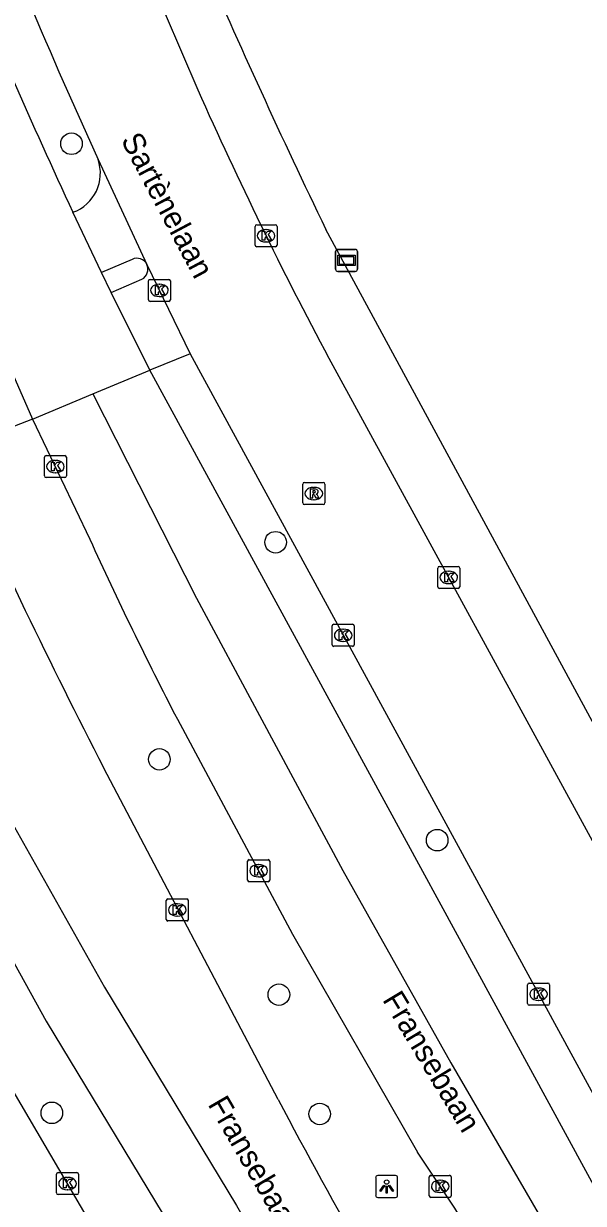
# Model space of a CAD drawing. Extents: x 157767 to 159171, y 387842 to 389425.
# Drawn here: x 158517.1 to 158542.4, y 388319.1 to 388372.6 of the extents above; entities that cross this region are included whole.
import ezdxf

# ---------------------------------------------------------------- set-up
doc = ezdxf.new("R2010")
doc.units = 0
for name, color, linetype in [('IMGEO_Boom', 7, 'Continuous'), ('IMGEO_Fietspad_open', 7, 'Continuous'), ('IMGEO_Kolk', 7, 'Continuous'), ('IMGEO_Lichtpunt', 7, 'Continuous'), ('IMGEO_Openbare_ruimte_label', 7, 'Continuous'), ('IMGEO_Rijbaan_lokaal_gesloten', 7, 'Continuous'), ('IMGEO_Rijbaan_lokaal_open', 7, 'Continuous'), ('IMGEO_Rioolput', 7, 'Continuous'), ('IMGEO_Verklikker', 7, 'Continuous'), ('IMGEO_Voetpad_open', 7, 'Continuous')]:
    doc.layers.add(name, color=color, linetype=linetype)

msp = doc.modelspace()

# ---------------------------------------------------------------- linework, layer by layer
at = {"layer": 'IMGEO_Boom'}
for centre in [(158519.228, 388367.129), (158528.486, 388349.061), (158523.215, 388339.218), (158535.816, 388335.554), (158528.635, 388328.551), (158518.336, 388323.19), (158530.487, 388323.141)]:
    msp.add_circle(centre, 0.489, dxfattribs=at)
at = {"layer": 'IMGEO_Fietspad_open'}
msp.add_lwpolyline([(158521.98, 388361.889), (158520.591, 388361.285)], dxfattribs=at)
for centre, radius, start, end in [((158518.657, 388365.792), 1.881, 289.7367, 19.4703), ((158522.198, 388361.433), 0.505, 26.5715, 115.5355)]:
    msp.add_arc(centre, radius, start, end, dxfattribs=at)
at = {"layer": 'IMGEO_Kolk'}
for p, q in [((158527.554, 388362.533), (158527.554, 388363.385)), ((158527.629, 388363.459), (158528.481, 388363.459)), ((158528.042, 388363.239), (158528.067, 388363.239)), ((158528.555, 388363.385), (158528.555, 388362.533)), ((158528.065, 388362.679), (158528.04, 388362.679)), ((158528.481, 388362.459), (158527.629, 388362.459)), ((158522.716, 388360.056), (158522.716, 388360.908)), ((158522.791, 388360.982), (158523.643, 388360.982)), ((158523.204, 388360.762), (158523.229, 388360.762)), ((158523.717, 388360.908), (158523.717, 388360.056)), ((158523.643, 388359.982), (158522.791, 388359.982)), ((158523.227, 388360.202), (158523.202, 388360.202)), ((158518.073, 388352.993), (158518.925, 388352.993)), ((158517.998, 388352.067), (158517.998, 388352.919)), ((158518.486, 388352.773), (158518.511, 388352.773)), ((158518.999, 388352.919), (158518.999, 388352.067)), ((158518.925, 388351.993), (158518.073, 388351.993)), ((158518.509, 388352.213), (158518.484, 388352.213)), ((158535.84, 388347.041), (158535.84, 388347.893)), ((158535.915, 388347.967), (158536.767, 388347.967)), ((158536.328, 388347.747), (158536.353, 388347.747)), ((158536.841, 388347.893), (158536.841, 388347.041)), ((158536.351, 388347.187), (158536.326, 388347.187)), ((158536.767, 388346.967), (158535.915, 388346.967)), ((158531.05, 388344.417), (158531.05, 388345.269)), ((158531.125, 388345.343), (158531.977, 388345.343)), ((158531.538, 388345.123), (158531.563, 388345.123)), ((158532.051, 388345.269), (158532.051, 388344.417)), ((158531.561, 388344.563), (158531.536, 388344.563)), ((158531.977, 388344.343), (158531.125, 388344.343)), ((158527.217, 388333.744), (158527.217, 388334.596)), ((158527.292, 388334.67), (158528.144, 388334.67)), ((158527.705, 388334.45), (158527.73, 388334.45)), ((158528.218, 388334.596), (158528.218, 388333.744)), ((158527.728, 388333.89), (158527.703, 388333.89)), ((158528.144, 388333.67), (158527.292, 388333.67)), ((158523.526, 388331.964), (158523.526, 388332.816)), ((158523.601, 388332.89), (158524.453, 388332.89)), ((158524.014, 388332.67), (158524.039, 388332.67)), ((158524.527, 388332.816), (158524.527, 388331.964)), ((158524.453, 388331.89), (158523.601, 388331.89)), ((158524.037, 388332.11), (158524.012, 388332.11)), ((158539.913, 388328.145), (158539.913, 388328.997)), ((158539.988, 388329.071), (158540.84, 388329.071)), ((158540.914, 388328.997), (158540.914, 388328.145)), ((158540.401, 388328.851), (158540.426, 388328.851)), ((158540.84, 388328.071), (158539.988, 388328.071)), ((158540.424, 388328.291), (158540.399, 388328.291)), ((158518.546, 388319.559), (158518.546, 388320.411)), ((158518.621, 388320.485), (158519.473, 388320.485)), ((158519.547, 388320.411), (158519.547, 388319.559)), ((158519.034, 388320.265), (158519.059, 388320.265)), ((158535.452, 388319.432), (158535.452, 388320.284)), ((158535.527, 388320.358), (158536.379, 388320.358)), ((158535.94, 388320.138), (158535.965, 388320.138)), ((158536.453, 388320.284), (158536.453, 388319.432)), ((158519.473, 388319.485), (158518.621, 388319.485)), ((158519.057, 388319.705), (158519.032, 388319.705)), ((158536.379, 388319.358), (158535.527, 388319.358)), ((158535.963, 388319.578), (158535.938, 388319.578))]:
    msp.add_line(p, q, dxfattribs=at)
for points in [[(158527.554, 388362.533), (158527.554, 388363.385)], [(158527.629, 388363.459), (158528.481, 388363.459)], [(158527.875, 388363.159), (158527.998, 388363.159), (158527.998, 388363.008), (158528.128, 388363.159), (158528.292, 388363.159), (158528.146, 388363.008), (158528.299, 388362.759), (158528.147, 388362.759), (158528.062, 388362.923), (158527.998, 388362.856), (158527.998, 388362.759), (158527.875, 388362.759), (158527.875, 388363.159)], [(158528.555, 388363.385), (158528.555, 388362.533)], [(158528.481, 388362.459), (158527.629, 388362.459)], [(158522.716, 388360.056), (158522.716, 388360.908)], [(158522.791, 388360.982), (158523.643, 388360.982)], [(158523.037, 388360.682), (158523.16, 388360.682), (158523.16, 388360.531), (158523.29, 388360.682), (158523.454, 388360.682), (158523.308, 388360.531), (158523.461, 388360.282), (158523.309, 388360.282), (158523.224, 388360.446), (158523.16, 388360.379), (158523.16, 388360.282), (158523.037, 388360.282), (158523.037, 388360.682)], [(158523.717, 388360.908), (158523.717, 388360.056)], [(158523.643, 388359.982), (158522.791, 388359.982)], [(158518.073, 388352.993), (158518.925, 388352.993)], [(158517.998, 388352.067), (158517.998, 388352.919)], [(158518.319, 388352.693), (158518.442, 388352.693), (158518.442, 388352.542), (158518.572, 388352.693), (158518.736, 388352.693), (158518.59, 388352.542), (158518.743, 388352.293), (158518.591, 388352.293), (158518.506, 388352.457), (158518.442, 388352.39), (158518.442, 388352.293), (158518.319, 388352.293), (158518.319, 388352.693)], [(158518.999, 388352.919), (158518.999, 388352.067)], [(158518.925, 388351.993), (158518.073, 388351.993)], [(158535.84, 388347.041), (158535.84, 388347.893)], [(158535.915, 388347.967), (158536.767, 388347.967)], [(158536.161, 388347.667), (158536.284, 388347.667), (158536.284, 388347.516), (158536.414, 388347.667), (158536.578, 388347.667), (158536.432, 388347.516), (158536.585, 388347.267), (158536.433, 388347.267), (158536.348, 388347.431), (158536.284, 388347.364), (158536.284, 388347.267), (158536.161, 388347.267), (158536.161, 388347.667)], [(158536.841, 388347.893), (158536.841, 388347.041)], [(158536.767, 388346.967), (158535.915, 388346.967)], [(158531.05, 388344.417), (158531.05, 388345.269)], [(158531.125, 388345.343), (158531.977, 388345.343)], [(158531.371, 388345.043), (158531.494, 388345.043), (158531.494, 388344.892), (158531.624, 388345.043), (158531.788, 388345.043), (158531.642, 388344.892), (158531.795, 388344.643), (158531.643, 388344.643), (158531.558, 388344.807), (158531.494, 388344.74), (158531.494, 388344.643), (158531.371, 388344.643), (158531.371, 388345.043)], [(158532.051, 388345.269), (158532.051, 388344.417)], [(158531.977, 388344.343), (158531.125, 388344.343)], [(158527.217, 388333.744), (158527.217, 388334.596)], [(158527.292, 388334.67), (158528.144, 388334.67)], [(158527.538, 388334.37), (158527.661, 388334.37), (158527.661, 388334.219), (158527.791, 388334.37), (158527.955, 388334.37), (158527.809, 388334.219), (158527.962, 388333.97), (158527.81, 388333.97), (158527.725, 388334.134), (158527.661, 388334.067), (158527.661, 388333.97), (158527.538, 388333.97), (158527.538, 388334.37)], [(158528.218, 388334.596), (158528.218, 388333.744)], [(158528.144, 388333.67), (158527.292, 388333.67)], [(158523.526, 388331.964), (158523.526, 388332.816)], [(158523.601, 388332.89), (158524.453, 388332.89)], [(158524.527, 388332.816), (158524.527, 388331.964)], [(158523.847, 388332.59), (158523.97, 388332.59), (158523.97, 388332.439), (158524.1, 388332.59), (158524.264, 388332.59), (158524.118, 388332.439), (158524.271, 388332.19), (158524.119, 388332.19), (158524.034, 388332.354), (158523.97, 388332.287), (158523.97, 388332.19), (158523.847, 388332.19), (158523.847, 388332.59)], [(158524.453, 388331.89), (158523.601, 388331.89)], [(158539.913, 388328.145), (158539.913, 388328.997)], [(158539.988, 388329.071), (158540.84, 388329.071)], [(158540.914, 388328.997), (158540.914, 388328.145)], [(158540.234, 388328.771), (158540.357, 388328.771), (158540.357, 388328.62), (158540.487, 388328.771), (158540.651, 388328.771), (158540.505, 388328.62), (158540.658, 388328.371), (158540.506, 388328.371), (158540.421, 388328.535), (158540.357, 388328.468), (158540.357, 388328.371), (158540.234, 388328.371), (158540.234, 388328.771)], [(158540.84, 388328.071), (158539.988, 388328.071)], [(158518.546, 388319.559), (158518.546, 388320.411)], [(158518.621, 388320.485), (158519.473, 388320.485)], [(158519.547, 388320.411), (158519.547, 388319.559)], [(158518.867, 388320.185), (158518.99, 388320.185), (158518.99, 388320.034), (158519.12, 388320.185), (158519.284, 388320.185), (158519.138, 388320.034), (158519.291, 388319.785), (158519.139, 388319.785), (158519.054, 388319.949), (158518.99, 388319.882), (158518.99, 388319.785), (158518.867, 388319.785), (158518.867, 388320.185)], [(158535.452, 388319.432), (158535.452, 388320.284)], [(158535.527, 388320.358), (158536.379, 388320.358)], [(158535.773, 388320.058), (158535.896, 388320.058), (158535.896, 388319.907), (158536.026, 388320.058), (158536.19, 388320.058), (158536.044, 388319.907), (158536.197, 388319.658), (158536.045, 388319.658), (158535.96, 388319.822), (158535.896, 388319.755), (158535.896, 388319.658), (158535.773, 388319.658), (158535.773, 388320.058)], [(158536.453, 388320.284), (158536.453, 388319.432)], [(158519.473, 388319.485), (158518.621, 388319.485)], [(158536.379, 388319.358), (158535.527, 388319.358)]]:
    msp.add_lwpolyline(points, dxfattribs=at)
for centre, start, end in [((158527.631, 388363.383), 91.552, 178.448), ((158527.631, 388363.383), 91.552, 178.448), ((158528.479, 388363.383), 1.552, 88.448), ((158528.479, 388363.383), 1.552, 88.448), ((158527.631, 388362.535), 181.552, 268.448), ((158527.631, 388362.535), 181.552, 268.448), ((158528.479, 388362.535), 271.552, 358.448), ((158528.479, 388362.535), 271.552, 358.448), ((158522.793, 388360.906), 91.552, 178.448), ((158522.793, 388360.906), 91.552, 178.448), ((158523.641, 388360.906), 1.552, 88.448), ((158523.641, 388360.906), 1.552, 88.448), ((158522.793, 388360.058), 181.552, 268.448), ((158522.793, 388360.058), 181.552, 268.448), ((158523.641, 388360.058), 271.552, 358.448), ((158523.641, 388360.058), 271.552, 358.448), ((158518.075, 388352.917), 91.552, 178.448), ((158518.075, 388352.917), 91.552, 178.448), ((158518.923, 388352.917), 1.552, 88.448), ((158518.923, 388352.917), 1.552, 88.448), ((158518.075, 388352.069), 181.552, 268.448), ((158518.075, 388352.069), 181.552, 268.448), ((158518.923, 388352.069), 271.552, 358.448), ((158518.923, 388352.069), 271.552, 358.448), ((158535.917, 388347.891), 91.552, 178.448), ((158535.917, 388347.891), 91.552, 178.448), ((158536.765, 388347.891), 1.552, 88.448), ((158536.765, 388347.891), 1.552, 88.448), ((158535.917, 388347.043), 181.552, 268.448), ((158535.917, 388347.043), 181.552, 268.448), ((158536.765, 388347.043), 271.552, 358.448), ((158536.765, 388347.043), 271.552, 358.448), ((158531.127, 388345.267), 91.552, 178.448), ((158531.127, 388345.267), 91.552, 178.448), ((158531.975, 388345.267), 1.552, 88.448), ((158531.975, 388345.267), 1.552, 88.448), ((158531.127, 388344.419), 181.552, 268.448), ((158531.127, 388344.419), 181.552, 268.448), ((158531.975, 388344.419), 271.552, 358.448), ((158531.975, 388344.419), 271.552, 358.448), ((158527.294, 388334.594), 91.552, 178.448), ((158527.294, 388334.594), 91.552, 178.448), ((158528.142, 388334.594), 1.552, 88.448), ((158528.142, 388334.594), 1.552, 88.448), ((158527.294, 388333.746), 181.552, 268.448), ((158527.294, 388333.746), 181.552, 268.448), ((158528.142, 388333.746), 271.552, 358.448), ((158528.142, 388333.746), 271.552, 358.448), ((158523.603, 388332.814), 91.552, 178.448), ((158523.603, 388332.814), 91.552, 178.448), ((158524.451, 388332.814), 1.552, 88.448), ((158524.451, 388332.814), 1.552, 88.448), ((158523.603, 388331.966), 181.552, 268.448), ((158523.603, 388331.966), 181.552, 268.448), ((158524.451, 388331.966), 271.552, 358.448), ((158524.451, 388331.966), 271.552, 358.448), ((158539.99, 388328.995), 91.552, 178.448), ((158539.99, 388328.995), 91.552, 178.448), ((158540.838, 388328.995), 1.552, 88.448), ((158540.838, 388328.995), 1.552, 88.448), ((158539.99, 388328.147), 181.552, 268.448), ((158539.99, 388328.147), 181.552, 268.448), ((158540.838, 388328.147), 271.552, 358.448), ((158540.838, 388328.147), 271.552, 358.448), ((158518.623, 388320.409), 91.552, 178.448), ((158518.623, 388320.409), 91.552, 178.448), ((158519.471, 388320.409), 1.552, 88.448), ((158519.471, 388320.409), 1.552, 88.448), ((158535.529, 388320.282), 91.552, 178.448), ((158535.529, 388320.282), 91.552, 178.448), ((158536.377, 388320.282), 1.552, 88.448), ((158536.377, 388320.282), 1.552, 88.448), ((158518.623, 388319.561), 181.552, 268.448), ((158518.623, 388319.561), 181.552, 268.448), ((158519.471, 388319.561), 271.552, 358.448), ((158519.471, 388319.561), 271.552, 358.448), ((158535.529, 388319.434), 181.552, 268.448), ((158535.529, 388319.434), 181.552, 268.448), ((158536.377, 388319.434), 271.552, 358.448), ((158536.377, 388319.434), 271.552, 358.448)]:
    msp.add_arc(centre, 0.0765, start, end, dxfattribs=at)
for centre, major_axis, ratio, start_param, end_param in [((158528.041, 388362.959), (-0.387, 0.002), 0.722429, 4.712389, 7.853982), ((158528.066, 388362.959), (-0.39, 0.002), 0.717154, 1.570796, 4.712389), ((158523.203, 388360.482), (-0.387, 0.002), 0.722429, 4.712389, 7.853982), ((158523.228, 388360.482), (-0.39, 0.002), 0.717154, 1.570796, 4.712389), ((158518.485, 388352.493), (-0.387, 0.002), 0.722429, 4.712389, 7.853982), ((158518.51, 388352.493), (-0.39, 0.002), 0.717154, 1.570796, 4.712389), ((158536.327, 388347.467), (-0.387, 0.002), 0.722429, 4.712389, 7.853982), ((158536.352, 388347.467), (-0.39, 0.002), 0.717154, 1.570796, 4.712389), ((158531.537, 388344.843), (-0.387, 0.002), 0.722429, 4.712389, 7.853982), ((158531.562, 388344.843), (-0.39, 0.002), 0.717154, 1.570796, 4.712389), ((158527.704, 388334.17), (-0.387, 0.002), 0.722429, 4.712389, 7.853982), ((158527.729, 388334.17), (-0.39, 0.002), 0.717154, 1.570796, 4.712389), ((158524.013, 388332.39), (-0.387, 0.002), 0.722429, 4.712389, 7.853982), ((158524.038, 388332.39), (-0.39, 0.002), 0.717154, 1.570796, 4.712389), ((158540.4, 388328.571), (-0.387, 0.002), 0.722429, 4.712389, 7.853982), ((158540.425, 388328.571), (-0.39, 0.002), 0.717154, 1.570796, 4.712389), ((158519.033, 388319.985), (-0.387, 0.002), 0.722429, 4.712389, 7.853982), ((158519.058, 388319.985), (-0.39, 0.002), 0.717154, 1.570796, 4.712389), ((158535.939, 388319.858), (-0.387, 0.002), 0.722429, 4.712389, 7.853982), ((158535.964, 388319.858), (-0.39, 0.002), 0.717154, 1.570796, 4.712389)]:
    msp.add_ellipse(centre, major_axis=major_axis, ratio=ratio, start_param=start_param, end_param=end_param, dxfattribs=at)
at = {"layer": 'IMGEO_Lichtpunt'}
for p, q in [((158533.025, 388320.255), (158533.025, 388319.448)), ((158533.025, 388320.255), (158533.025, 388319.448)), ((158533.927, 388320.35), (158533.119, 388320.35)), ((158533.927, 388320.35), (158533.119, 388320.35)), ((158534.021, 388319.448), (158534.021, 388320.255)), ((158534.021, 388319.448), (158534.021, 388320.255)), ((158533.119, 388319.354), (158533.927, 388319.354)), ((158533.119, 388319.354), (158533.927, 388319.354))]:
    msp.add_line(p, q, dxfattribs=at)
for points in [[(158533.399, 388319.919), (158533.438, 388319.891), (158533.25, 388319.629), (158533.212, 388319.656), (158533.399, 388319.919)], [(158533.501, 388319.871), (158533.548, 388319.871), (158533.548, 388319.549), (158533.501, 388319.549), (158533.501, 388319.871)], [(158533.611, 388319.891), (158533.649, 388319.918), (158533.836, 388319.656), (158533.797, 388319.628), (158533.611, 388319.891)]]:
    msp.add_lwpolyline(points, dxfattribs=at)
msp.add_circle((158533.524, 388320.053), 0.0994, dxfattribs=at)
for centre, start, end in [((158533.119, 388320.255), 90, 180), ((158533.119, 388320.255), 90, 180), ((158533.927, 388320.255), 0, 90), ((158533.927, 388320.255), 0, 90), ((158533.119, 388319.448), 180, 270), ((158533.119, 388319.448), 180, 270), ((158533.927, 388319.448), 270, 0), ((158533.927, 388319.448), 270, 360)]:
    msp.add_arc(centre, 0.0946, start, end, dxfattribs=at)
at = {"layer": 'IMGEO_Rijbaan_lokaal_gesloten'}
for points in [[(158520.591, 388361.285), (158519.292, 388364.022)], [(158521.03, 388360.379), (158520.591, 388361.285)], [(158522.774, 388356.867), (158521.03, 388360.379)], [(158515.864, 388358.245), (158517.464, 388354.644)], [(158520.193, 388355.786), (158522.774, 388356.867)], [(158556.51, 388294.945), (158522.774, 388356.867)], [(158517.464, 388354.644), (158520.193, 388355.786)], [(158520.193, 388355.786), (158524.893, 388346.524), (158527.752, 388341.202), (158531.535, 388334.178), (158536.428, 388325.454), (158544.459, 388311.65), (158555.339, 388288.902)], [(158517.464, 388354.644), (158520.058, 388349.207)], [(158510.149, 388348.16), (158516.097, 388337.104), (158520.719, 388328.892), (158526.706, 388318.987), (158530.891, 388311.658), (158535.936, 388303.26)], [(158524.031, 388341.037), (158529.258, 388331.294), (158534.917, 388321.411)], [(158528.598, 388323.799), (158520.698, 388338.819)]]:
    msp.add_lwpolyline(points, dxfattribs=at)
for centre, radius, start, end in [((158748.293, 388471.013), 252.761, 202.04147, 205.0423), ((158763.078, 388464.134), 272.859, 203.9844, 207.33977), ((158684.085, 388423.921), 180.242, 204.48915, 207.37736), ((158776.555, 388455.267), 280.654, 207.9327, 211.32432), ((158344.877, 388193.312), 229.182, 30.48594, 33.98258)]:
    msp.add_arc(centre, radius, start, end, dxfattribs=at)
at = {"layer": 'IMGEO_Rijbaan_lokaal_open'}
for points in [[(158519.147, 388383.327), (158520.52, 388379.92), (158524.959, 388369.576)], [(158518.655, 388370.393), (158520.43, 388366.419)], [(158520.43, 388366.419), (158522.65, 388361.659)], [(158522.65, 388361.659), (158524.616, 388357.602)], [(158524.616, 388357.602), (158544.005, 388321.982), (158558.222, 388295.881)], [(158530.905, 388357.407), (158544.005, 388333.408), (158561.354, 388301.588), (158565.72, 388294.121)], [(158532.05, 388297.782), (158526.372, 388307.483), (158502.602, 388348.033)]]:
    msp.add_lwpolyline(points, dxfattribs=at)
for centre, radius, start, end in [((158976.91, 388567.843), 498.984, 201.44723, 203.30997), ((158694.482, 388444.871), 185.493, 203.94877, 208.13322)]:
    msp.add_arc(centre, radius, start, end, dxfattribs=at)
at = {"layer": 'IMGEO_Rioolput'}
for p, q in [((158529.719, 388350.845), (158529.719, 388351.697)), ((158529.794, 388351.771), (158530.646, 388351.771)), ((158530.207, 388351.551), (158530.232, 388351.551)), ((158530.72, 388351.697), (158530.72, 388350.845)), ((158530.23, 388350.991), (158530.205, 388350.991)), ((158530.646, 388350.771), (158529.794, 388350.771))]:
    msp.add_line(p, q, dxfattribs=at)
for points in [[(158529.719, 388350.845), (158529.719, 388351.697)], [(158529.794, 388351.771), (158530.646, 388351.771)], [(158530.308, 388351.469), (158530.056, 388351.471), (158530.056, 388351.071)], [(158530.234, 388351.39), (158530.18, 388351.39), (158530.18, 388351.309)], [(158530.72, 388351.697), (158530.72, 388350.845)], [(158530.056, 388351.071), (158530.18, 388351.071), (158530.18, 388351.233), (158530.191, 388351.233)], [(158530.18, 388351.309), (158530.232, 388351.309)], [(158530.238, 388351.204), (158530.309, 388351.071), (158530.449, 388351.071), (158530.384, 388351.197)], [(158530.646, 388350.771), (158529.794, 388350.771)]]:
    msp.add_lwpolyline(points, dxfattribs=at)
for centre, radius, start, end in [((158529.796, 388351.695), 0.0765, 91.552, 178.448), ((158529.796, 388351.695), 0.0765, 91.552, 178.448), ((158530.24, 388351.294), 0.0964, 77.0061, 93.1865), ((158530.254, 388351.351), 0.0378, 276.6634, 79.6772), ((158530.307, 388351.359), 0.109, 350.3612, 89.416), ((158530.644, 388351.695), 0.0765, 1.552, 88.448), ((158530.644, 388351.695), 0.0765, 1.552, 88.448), ((158530.19, 388351.18), 0.0533, 26.0293, 88.6989), ((158530.216, 388351.498), 0.19, 274.7715, 282.9687), ((158530.305, 388351.359), 0.112, 277.5842, 350.9817), ((158530.289, 388351.144), 0.108, 29.5134, 73.7905), ((158529.796, 388350.847), 0.0765, 181.552, 268.448), ((158529.796, 388350.847), 0.0765, 181.552, 268.448), ((158530.644, 388350.847), 0.0765, 271.552, 358.448), ((158530.644, 388350.847), 0.0765, 271.552, 358.448)]:
    msp.add_arc(centre, radius, start, end, dxfattribs=at)
for centre, major_axis, ratio, start_param, end_param in [((158530.206, 388351.271), (-0.387, 0.002), 0.722429, 4.712389, 7.853982), ((158530.231, 388351.271), (-0.39, 0.002), 0.717154, 1.570796, 4.712389)]:
    msp.add_ellipse(centre, major_axis=major_axis, ratio=ratio, start_param=start_param, end_param=end_param, dxfattribs=at)
at = {"layer": 'IMGEO_Verklikker'}
for p, q in [((158531.205, 388361.442), (158531.205, 388362.242)), ((158531.205, 388362.242), (158531.205, 388361.442)), ((158531.305, 388362.342), (158532.095, 388362.342)), ((158532.095, 388362.342), (158531.305, 388362.342)), ((158532.195, 388362.242), (158532.195, 388361.442)), ((158532.195, 388361.442), (158532.195, 388362.242)), ((158532.095, 388361.342), (158531.305, 388361.342)), ((158531.305, 388361.342), (158532.095, 388361.342))]:
    msp.add_line(p, q, dxfattribs=at)
for points in [[(158531.306, 388362.074), (158532.094, 388362.074), (158532.094, 388361.61), (158531.306, 388361.61), (158531.306, 388362.074)], [(158531.371, 388362.009), (158531.371, 388361.675), (158532.029, 388361.675), (158532.029, 388362.009), (158531.371, 388362.009)]]:
    msp.add_lwpolyline(points, dxfattribs=at)
for centre, start, end in [((158531.305, 388362.242), 90, 180), ((158531.305, 388362.242), 90, 180), ((158532.095, 388362.242), 0, 90), ((158532.095, 388362.242), 360, 90), ((158531.305, 388361.442), 180, 270), ((158531.305, 388361.442), 180, 270), ((158532.095, 388361.442), 270, 0), ((158532.095, 388361.442), 270, 0)]:
    msp.add_arc(centre, 0.1, start, end, dxfattribs=at)
at = {"layer": 'IMGEO_Voetpad_open'}
for points in [[(158543.035, 388340.593), (158530.768, 388363.248)], [(158521.03, 388360.379), (158522.424, 388360.986)], [(158524.616, 388357.602), (158522.774, 388356.867)], [(158517.464, 388354.644), (158513.779, 388353.22)], [(158512.335, 388337.725), (158518.083, 388327.354), (158524.075, 388317.441), (158528.055, 388310.472)]]:
    msp.add_lwpolyline(points, dxfattribs=at)
for centre, radius, start, end in [((158820.366, 388503.517), 321.78, 203.38491, 205.84367), ((158522.159, 388361.449), 0.534, 299.7388, 23.1361)]:
    msp.add_arc(centre, radius, start, end, dxfattribs=at)

# ---------------------------------------------------------------- texts
at = {"layer": 'IMGEO_Openbare_ruimte_label'}
for s, rotation, p in [('Sartènelaan', 298.0253, (158521.448, 388367.3)), ('Fransebaan', 301.0522, (158533.307, 388328.322)), ('Fransebaan', 300.1286, (158525.39, 388323.582))]:
    msp.add_text(s, height=1, rotation=rotation, dxfattribs=at).set_placement(p)

doc.saveas('drawing.dxf')
